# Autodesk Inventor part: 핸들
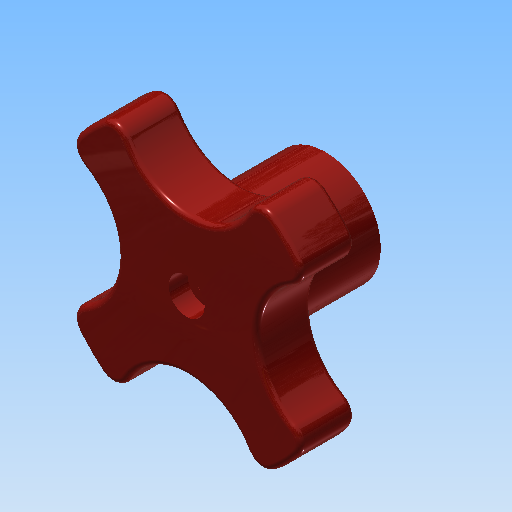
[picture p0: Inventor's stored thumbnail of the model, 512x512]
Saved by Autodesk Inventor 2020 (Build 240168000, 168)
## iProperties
Created: 2018-01
Part Number: 핸들
Material: ABS 플라스틱
Document SubType Name: Modeling
Designer: mduedu
Density: 1 g/cm^3
Appearance: 주황색-빨간색
Author: mduedu
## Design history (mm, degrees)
sketch "스케치1"
  geometry: C1 r 10 at (0, 0); C2 r 25 at (0, 0); 1 further point
  constraints: 2 centre point, 2 coincident
  dimensions: "d0" = 20 diameter of C1; "d1" = 50 diameter of C2
extrude "돌출1" new body sketch "스케치1" distance "d2" = 15; taper "d3" = 0 deg
extrude "돌출2" join sketch "스케치1" distance "d4" = 10; taper "d5" = 0 deg
sketch "스케치2" dims "d8" = 15
  geometry: L1 (-6, -6)-(-4.5, -6); L2 (6, -6)-(6, -4.5); L3 (6, 6)-(4.5, 6); L4 (-6, 6)-(-6, 4.5); L5 (-6, -6)-(6, 6); L6 (6, -6)-(-6, 6); L7 (-4.5, 6)-(-6, 6); L8 (4.5, 6)-(-4.5, 6); L9 (6, 4.5)-(6, 6); L10 (6, -4.5)-(6, 4.5); L11 (4.5, -6)-(6, -6); L12 (-4.5, -6)-(4.5, -6); L13 (-6, -4.5)-(-6, -6); L14 (-6, 4.5)-(-6, -4.5); 2 further points
  constraints: 28 end point, 18 parallel, 9 perpendicular, 3 horizontal, 2 midpoint, 1 coincident, 10 other
  dimensions: "d6" = 12 distance of L4.start L3.start; "d7" = 12 distance of L3.start L2.start
extrude "돌출3" cut sketch "스케치2" distance "d9" = 15; taper "d10" = 0 deg
sketch "스케치3"
  geometry: C1 r 12.5 at (25, 0); 2 further points
  constraints: 2 horizontal alignment, 1 centre point, 1 other
  dimensions: "d14" = 25 diameter of C1
extrude "돌출4" cut sketch "스케치3" extent not by distance; stored distance "d15" = 15; taper "d16" = 0 deg
fillet "모깎기1" dims "d20" = 3
fillet "모깎기2" dims "d24" = 1
sketch "스케치4"
  geometry: 2 further points
  constraints: 1 coincident
sketch "스케치5"
  geometry: 2 further points
  constraints: 1 coincident
hole "구멍1" sketch "스케치5" at (0, 0) diameter "d25" = 3.4; stored, may be unused: countersink angle "d29" = 90 deg, drill point angle "d31" = 0 deg; dims "d26" = 6, "d27" = 6.5, "d28" = 3.4, "d30" = 8
node "솔리드1"
pattern_circular "원형 패턴1" dims angle "d18" = 360 deg
pattern_circular "원형 패턴2" dims angle "d22" = 360 deg
node "투영된 루프1"
